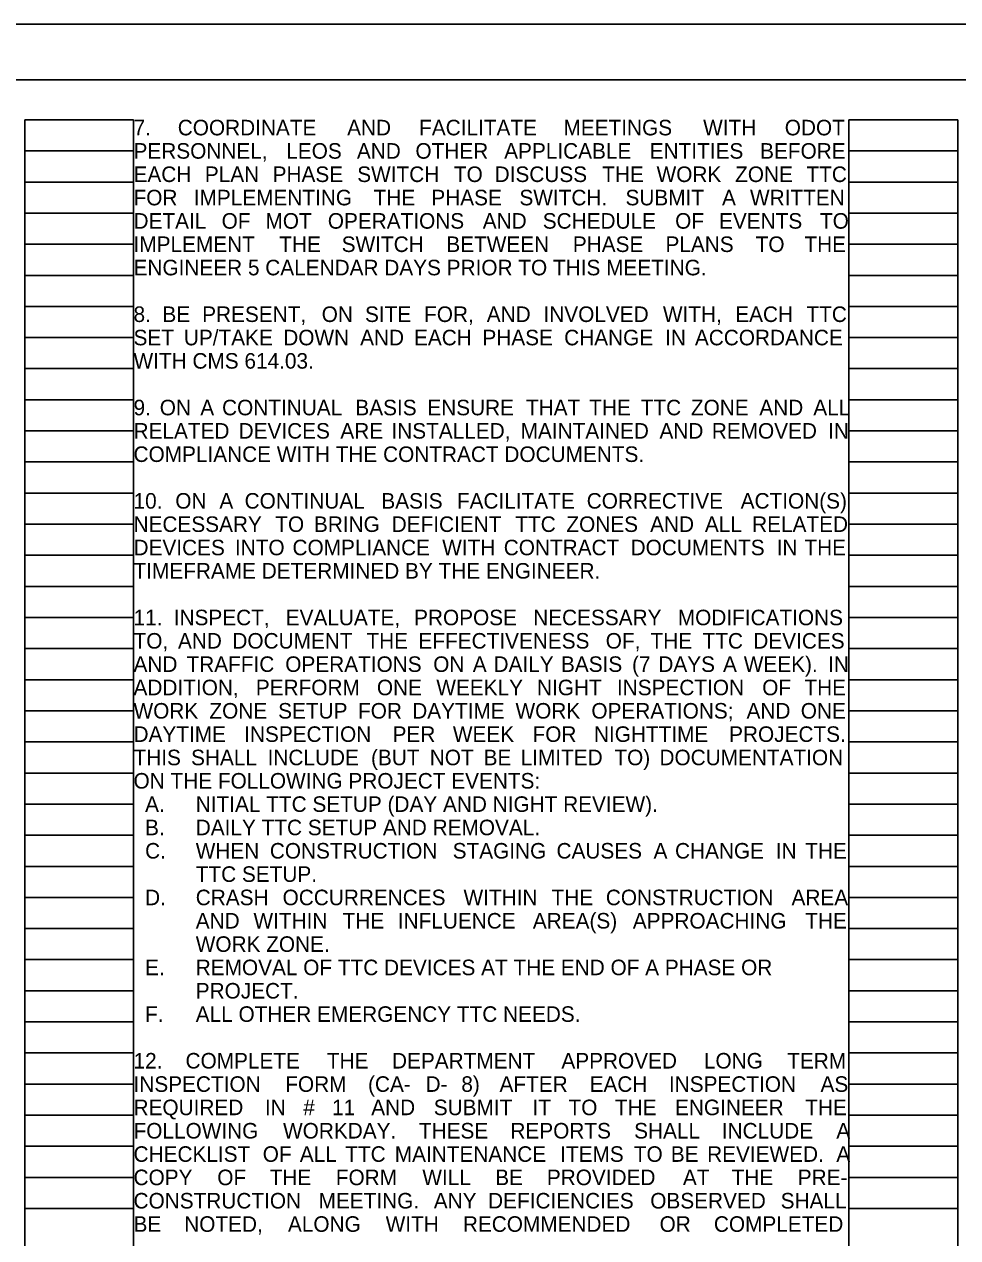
# Model space of a CAD drawing. Extents: x 0 to 34, y 0 to 22.
# Drawn here: x 8.84 to 17.24, y 11.08 to 22 of the extents above; entities that cross this region are included whole.
import ezdxf

# ---------------------------------------------------------------- set-up
doc = ezdxf.new("R2010")
doc.units = 0
for name, color, linetype in [('SH_Border', 7, 'Continuous'), ('SH_Cut_Line', 7, 'Continuous'), ('SH_Data', 7, 'Continuous'), ('SH_Text', 7, 'Continuous')]:
    doc.layers.add(name, color=color, linetype=linetype)

msp = doc.modelspace()

# ---------------------------------------------------------------- linework, layer by layer
at = {"layer": 'SH_Border'}
msp.add_lwpolyline([(1.5, 21.5), (33.5, 21.5), (33.5, 0.5), (1.5, 0.5)], close=True, dxfattribs=at)
at = {"layer": 'SH_Cut_Line'}
msp.add_lwpolyline([(0, 0), (34, 0), (34, 22), (0, 22)], close=True, dxfattribs=at)
at = {"layer": 'SH_Data'}
for p, q in [((8.84, 0.98), (8.84, 21.14)), ((8.84, 21.14), (9.82, 21.14)), ((9.82, 0.98), (9.82, 21.14)), ((16.26, 0.98), (16.26, 21.14)), ((16.26, 21.14), (17.24, 21.14)), ((17.24, 0.98), (17.24, 21.14)), ((8.84, 20.86), (9.82, 20.86)), ((16.26, 20.86), (17.24, 20.86)), ((8.84, 20.58), (9.82, 20.58)), ((16.26, 20.58), (17.24, 20.58)), ((8.84, 20.3), (9.82, 20.3)), ((16.26, 20.3), (17.24, 20.3)), ((8.84, 20.02), (9.82, 20.02)), ((16.26, 20.02), (17.24, 20.02)), ((8.84, 19.74), (9.82, 19.74)), ((16.26, 19.74), (17.24, 19.74)), ((8.84, 19.46), (9.82, 19.46)), ((16.26, 19.46), (17.24, 19.46)), ((8.84, 19.18), (9.82, 19.18)), ((16.26, 19.18), (17.24, 19.18)), ((8.84, 18.9), (9.82, 18.9)), ((16.26, 18.9), (17.24, 18.9)), ((8.84, 18.62), (9.82, 18.62)), ((16.26, 18.62), (17.24, 18.62)), ((8.84, 18.34), (9.82, 18.34)), ((16.26, 18.34), (17.24, 18.34)), ((8.84, 18.06), (9.82, 18.06)), ((16.26, 18.06), (17.24, 18.06)), ((8.84, 17.78), (9.82, 17.78)), ((16.26, 17.78), (17.24, 17.78)), ((8.84, 17.5), (9.82, 17.5)), ((16.26, 17.5), (17.24, 17.5)), ((8.84, 17.22), (9.82, 17.22)), ((16.26, 17.22), (17.24, 17.22)), ((8.84, 16.94), (9.82, 16.94)), ((16.26, 16.94), (17.24, 16.94)), ((8.84, 16.66), (9.82, 16.66)), ((16.26, 16.66), (17.24, 16.66)), ((8.84, 16.38), (9.82, 16.38)), ((16.26, 16.38), (17.24, 16.38)), ((8.84, 16.1), (9.82, 16.1)), ((16.26, 16.1), (17.24, 16.1)), ((8.84, 15.82), (9.82, 15.82)), ((16.26, 15.82), (17.24, 15.82)), ((8.84, 15.54), (9.82, 15.54)), ((16.26, 15.54), (17.24, 15.54)), ((8.84, 15.26), (9.82, 15.26)), ((16.26, 15.26), (17.24, 15.26)), ((8.84, 14.98), (9.82, 14.98)), ((16.26, 14.98), (17.24, 14.98)), ((8.84, 14.7), (9.82, 14.7)), ((16.26, 14.7), (17.24, 14.7)), ((8.84, 14.42), (9.82, 14.42)), ((16.26, 14.42), (17.24, 14.42)), ((8.84, 14.14), (9.82, 14.14)), ((16.26, 14.14), (17.24, 14.14)), ((8.84, 13.86), (9.82, 13.86)), ((16.26, 13.86), (17.24, 13.86)), ((8.84, 13.58), (9.82, 13.58)), ((16.26, 13.58), (17.24, 13.58)), ((8.84, 13.3), (9.82, 13.3)), ((16.26, 13.3), (17.24, 13.3)), ((8.84, 13.02), (9.82, 13.02)), ((16.26, 13.02), (17.24, 13.02)), ((8.84, 12.74), (9.82, 12.74)), ((16.26, 12.74), (17.24, 12.74)), ((8.84, 12.46), (9.82, 12.46)), ((16.26, 12.46), (17.24, 12.46)), ((8.84, 12.18), (9.82, 12.18)), ((16.26, 12.18), (17.24, 12.18)), ((8.84, 11.9), (9.82, 11.9)), ((16.26, 11.9), (17.24, 11.9)), ((8.84, 11.62), (9.82, 11.62)), ((16.26, 11.62), (17.24, 11.62)), ((8.84, 11.34), (9.82, 11.34)), ((16.26, 11.34), (17.24, 11.34))]:
    msp.add_line(p, q, dxfattribs=at)

# ---------------------------------------------------------------- texts
at = {"layer": 'SH_Text'}
for s, p in [('7. ', (9.82, 21)), ('COORDINATE ', (10.218, 21)), ('AND ', (11.743, 21)), ('FACILITATE ', (12.391, 21)), ('MEETINGS ', (13.691, 21)), ('WITH ', (14.948, 21)), ('ODOT ', (15.683, 21)), ('PERSONNEL, ', (9.82, 20.79)), ('LEOS ', (11.195, 20.79)), ('AND ', (11.831, 20.79)), ('OTHER ', (12.358, 20.79)), ('APPLICABLE ', (13.157, 20.79)), ('ENTITIES ', (14.467, 20.79)), ('BEFORE ', (15.461, 20.79)), ('EACH ', (9.82, 20.58)), ('PLAN ', (10.462, 20.58)), ('PHASE ', (11.072, 20.58)), ('SWITCH ', (11.834, 20.58)), ('TO ', (12.704, 20.58)), ('DISCUSS ', (13.071, 20.58)), ('THE ', (14.039, 20.58)), ('WORK ', (14.529, 20.58)), ('ZONE ', (15.236, 20.58)), ('TTC ', (15.878, 20.58)), ('FOR ', (9.82, 20.37)), ('IMPLEMENTING ', (10.362, 20.37)), ('THE ', (11.981, 20.37)), ('PHASE ', (12.501, 20.37)), ('SWITCH. ', (13.294, 20.37)), ('SUBMIT ', (14.249, 20.37)), ('A ', (15.118, 20.37)), ('WRITTEN ', (15.37, 20.37)), ('DETAIL ', (9.82, 20.16)), ('OF ', (10.613, 20.16)), ('MOT ', (11.008, 20.16)), ('OPERATIONS ', (11.569, 20.16)), ('AND ', (12.964, 20.16)), ('SCHEDULE ', (13.504, 20.16)), ('OF ', (14.696, 20.16)), ('EVENTS ', (15.091, 20.16)), ('TO ', (16, 20.16)), ('IMPLEMENT ', (9.82, 19.95)), ('THE ', (11.132, 19.95)), ('SWITCH ', (11.694, 19.95)), ('BETWEEN ', (12.636, 19.95)), ('PHASE ', (13.775, 19.95)), ('PLANS ', (14.609, 19.95)), ('TO ', (15.421, 19.95)), ('THE ', (15.86, 19.95)), ('ENGINEER 5 CALENDAR DAYS PRIOR TO THIS MEETING.', (9.82, 19.74)), ('8. ', (9.82, 19.32)), ('BE ', (10.08, 19.32)), ('PRESENT, ', (10.438, 19.32)), ('ON ', (11.514, 19.32)), ('SITE ', (11.904, 19.32)), ('FOR, ', (12.436, 19.32)), ('AND ', (13, 19.32)), ('INVOLVED ', (13.511, 19.32)), ('WITH, ', (14.586, 19.32)), ('EACH ', (15.237, 19.32)), ('TTC ', (15.878, 19.32)), ('SET ', (9.82, 19.11)), ('UP/TAKE ', (10.273, 19.11)), ('DOWN ', (11.168, 19.11)), ('AND ', (11.86, 19.11)), ('EACH ', (12.345, 19.11)), ('PHASE ', (12.961, 19.11)), ('CHANGE ', (13.697, 19.11)), ('IN ', (14.606, 19.11)), ('ACCORDANCE ', (14.874, 19.11)), ('WITH CMS 614.03.', (9.82, 18.9)), ('9. ', (9.82, 18.48)), ('ON ', (10.056, 18.48)), ('A ', (10.421, 18.48)), ('CONTINUAL ', (10.617, 18.48)), ('BASIS ', (11.817, 18.48)), ('ENSURE ', (12.465, 18.48)), ('THAT ', (13.353, 18.48)), ('THE ', (13.922, 18.48)), ('TTC ', (14.386, 18.48)), ('ZONE ', (14.838, 18.48)), ('AND ', (15.454, 18.48)), ('ALL ', (15.94, 18.48)), ('RELATED ', (9.82, 18.27)), ('DEVICES ', (10.766, 18.27)), ('ARE ', (11.682, 18.27)), ('INSTALLED, ', (12.142, 18.27)), ('MAINTAINED ', (13.305, 18.27)), ('AND ', (14.555, 18.27)), ('REMOVED ', (15.026, 18.27)), ('IN ', (16.073, 18.27)), ('COMPLIANCE WITH THE CONTRACT DOCUMENTS.', (9.82, 18.06)), ('10. ', (9.82, 17.64)), ('ON ', (10.196, 17.64)), ('A ', (10.593, 17.64)), ('CONTINUAL ', (10.82, 17.64)), ('BASIS ', (12.051, 17.64)), ('FACILITATE ', (12.731, 17.64)), ('CORRECTIVE ', (13.9, 17.64)), ('ACTION(S) ', (15.286, 17.64)), ('NECESSARY ', (9.82, 17.43)), ('TO ', (11.096, 17.43)), ('BRING ', (11.444, 17.43)), ('DEFICIENT ', (12.144, 17.43)), ('TTC ', (13.257, 17.43)), ('ZONES ', (13.717, 17.43)), ('AND ', (14.471, 17.43)), ('ALL ', (14.964, 17.43)), ('RELATED ', (15.389, 17.43)), ('DEVICES ', (9.82, 17.22)), ('INTO ', (10.733, 17.22)), ('COMPLIANCE ', (11.251, 17.22)), ('WITH ', (12.599, 17.22)), ('CONTRACT ', (13.153, 17.22)), ('DOCUMENTS ', (14.295, 17.22)), ('IN ', (15.61, 17.22)), ('THE ', (15.86, 17.22)), ('TIMEFRAME DETERMINED BY THE ENGINEER.', (9.82, 17.01)), ('11. ', (9.82, 16.59)), ('INSPECT, ', (10.182, 16.59)), ('EVALUATE, ', (11.19, 16.59)), ('PROPOSE ', (12.346, 16.59)), ('NECESSARY ', (13.418, 16.59)), ('MODIFICATIONS ', (14.72, 16.59)), ('TO, ', (9.82, 16.38)), ('AND ', (10.22, 16.38)), ('DOCUMENT ', (10.71, 16.38)), ('THE ', (11.917, 16.38)), ('EFFECTIVENESS ', (12.385, 16.38)), ('OF, ', (14.071, 16.38)), ('THE ', (14.474, 16.38)), ('TTC ', (14.943, 16.38)), ('DEVICES ', (15.4, 16.38)), ('AND ', (9.82, 16.17)), ('TRAFFIC ', (10.297, 16.17)), ('OPERATIONS ', (11.186, 16.17)), ('ON ', (12.518, 16.17)), ('A ', (12.874, 16.17)), ('DAILY ', (13.061, 16.17)), ('BASIS ', (13.668, 16.17)), ('(7 ', (14.308, 16.17)), ('DAYS ', (14.545, 16.17)), ('A ', (15.127, 16.17)), ('WEEK). ', (15.314, 16.17)), ('IN ', (16.073, 16.17)), ('ADDITION, ', (9.82, 15.96)), ('PERFORM ', (10.921, 15.96)), ('ONE ', (12.011, 15.96)), ('WEEKLY ', (12.546, 15.96)), ('NIGHT ', (13.452, 15.96)), ('INSPECTION ', (14.172, 15.96)), ('OF ', (15.48, 15.96)), ('THE ', (15.86, 15.96)), ('WORK ', (9.82, 15.75)), ('ZONE ', (10.503, 15.75)), ('SETUP ', (11.122, 15.75)), ('FOR ', (11.841, 15.75)), ('DAYTIME ', (12.329, 15.75)), ('WORK ', (13.259, 15.75)), ('OPERATIONS; ', (13.942, 15.75)), ('AND ', (15.339, 15.75)), ('ONE ', (15.827, 15.75)), ('DAYTIME ', (9.82, 15.54)), ('INSPECTION ', (10.816, 15.54)), ('PER ', (12.152, 15.54)), ('WEEK ', (12.695, 15.54)), ('FOR ', (13.412, 15.54)), ('NIGHTTIME ', (13.965, 15.54)), ('PROJECTS. ', (15.182, 15.54)), ('THIS ', (9.82, 15.33)), ('SHALL ', (10.338, 15.33)), ('INCLUDE ', (11.027, 15.33)), ('(BUT ', (11.958, 15.33)), ('NOT ', (12.487, 15.33)), ('BE ', (12.972, 15.33)), ('LIMITED ', (13.305, 15.33)), ('TO) ', (14.149, 15.33)), ('DOCUMENTATION ', (14.555, 15.33)), ('ON THE FOLLOWING PROJECT EVENTS:', (9.82, 15.12)), ('  A. ', (9.82, 14.91)), ('NITIAL TTC SETUP (DAY AND NIGHT REVIEW).', (10.38, 14.91)), ('  B. ', (9.82, 14.7)), ('DAILY TTC SETUP AND REMOVAL.', (10.38, 14.7)), ('  C. ', (9.82, 14.49)), ('WHEN ', (10.38, 14.49)), ('CONSTRUCTION ', (11.047, 14.49)), ('STAGING ', (12.693, 14.49)), ('CAUSES ', (13.628, 14.49)), ('A ', (14.502, 14.49)), ('CHANGE ', (14.695, 14.49)), ('IN ', (15.602, 14.49)), ('THE ', (15.867, 14.49)), ('TTC SETUP.', (10.38, 14.28)), ('  D. ', (9.82, 14.07)), ('CRASH ', (10.38, 14.07)), ('OCCURRENCES ', (11.162, 14.07)), ('WITHIN ', (12.791, 14.07)), ('THE ', (13.583, 14.07)), ('CONSTRUCTION ', (14.072, 14.07)), ('AREA ', (15.744, 14.07)), ('AND ', (10.38, 13.86)), ('WITHIN ', (10.9, 13.86)), ('THE ', (11.702, 13.86)), ('INFLUENCE ', (12.199, 13.86)), ('AREA(S) ', (13.415, 13.86)), ('APPROACHING ', (14.315, 13.86)), ('THE ', (15.867, 13.86)), ('WORK ZONE.', (10.38, 13.65)), ('  E. ', (9.82, 13.44)), ('REMOVAL OF TTC DEVICES AT THE END OF A PHASE OR ', (10.38, 13.44)), ('PROJECT.', (10.38, 13.23)), ('  F. ', (9.82, 13.02)), ('ALL OTHER EMERGENCY TTC NEEDS.', (10.38, 13.02)), ('12. ', (9.82, 12.6)), ('COMPLETE ', (10.288, 12.6)), ('THE ', (11.56, 12.6)), ('DEPARTMENT ', (12.147, 12.6)), ('APPROVED ', (13.672, 12.6)), ('LONG ', (14.955, 12.6)), ('TERM ', (15.705, 12.6)), ('INSPECTION ', (9.82, 12.39)), ('FORM ', (11.186, 12.39)), ('(CA-', (11.931, 12.39)), ('D-', (12.449, 12.39)), ('8) ', (12.771, 12.39)), ('AFTER ', (13.115, 12.39)), ('EACH ', (13.926, 12.39)), ('INSPECTION ', (14.64, 12.39)), ('AS ', (16.005, 12.39)), ('REQUIRED ', (9.82, 12.18)), ('IN ', (11.003, 12.18)), ('# ', (11.348, 12.18)), ('11 ', (11.607, 12.18)), ('AND ', (11.96, 12.18)), ('SUBMIT ', (12.523, 12.18)), ('IT ', (13.412, 12.18)), ('TO ', (13.736, 12.18)), ('THE ', (14.154, 12.18)), ('ENGINEER ', (14.695, 12.18)), ('THE ', (15.867, 12.18)), ('FOLLOWING ', (9.82, 11.97)), ('WORKDAY. ', (11.166, 11.97)), ('THESE ', (12.389, 11.97)), ('REPORTS ', (13.213, 11.97)), ('SHALL ', (14.327, 11.97)), ('INCLUDE ', (15.116, 11.97)), ('A ', (16.147, 11.97)), ('CHECKLIST ', (9.82, 11.76)), ('OF ', (10.983, 11.76)), ('ALL ', (11.317, 11.76)), ('TTC ', (11.726, 11.76)), ('MAINTENANCE ', (12.172, 11.76)), ('ITEMS ', (13.661, 11.76)), ('TO ', (14.324, 11.76)), ('BE ', (14.657, 11.76)), ('REVIEWED. ', (14.984, 11.76)), ('A ', (16.147, 11.76)), ('COPY ', (9.82, 11.55)), ('OF ', (10.574, 11.55)), ('THE ', (11.046, 11.55)), ('FORM ', (11.641, 11.55)), ('WILL ', (12.42, 11.55)), ('BE ', (13.076, 11.55)), ('PROVIDED ', (13.541, 11.55)), ('AT ', (14.766, 11.55)), ('THE ', (15.205, 11.55)), ('PRE-', (15.8, 11.55)), ('CONSTRUCTION ', (9.82, 11.34)), ('MEETING. ', (11.486, 11.34)), ('ANY ', (12.523, 11.34)), ('DEFICIENCIES ', (13.012, 11.34)), ('OBSERVED ', (14.472, 11.34)), ('SHALL ', (15.646, 11.34)), ('BE ', (9.82, 11.13)), ('NOTED, ', (10.276, 11.13)), ('ALONG ', (11.21, 11.13)), ('WITH ', (12.09, 11.13)), ('RECOMMENDED ', (12.785, 11.13)), ('OR ', (14.556, 11.13)), ('COMPLETED ', (15.045, 11.13))]:
    msp.add_text(s, height=0.14, dxfattribs=at).set_placement(p)

doc.saveas('drawing.dxf')
